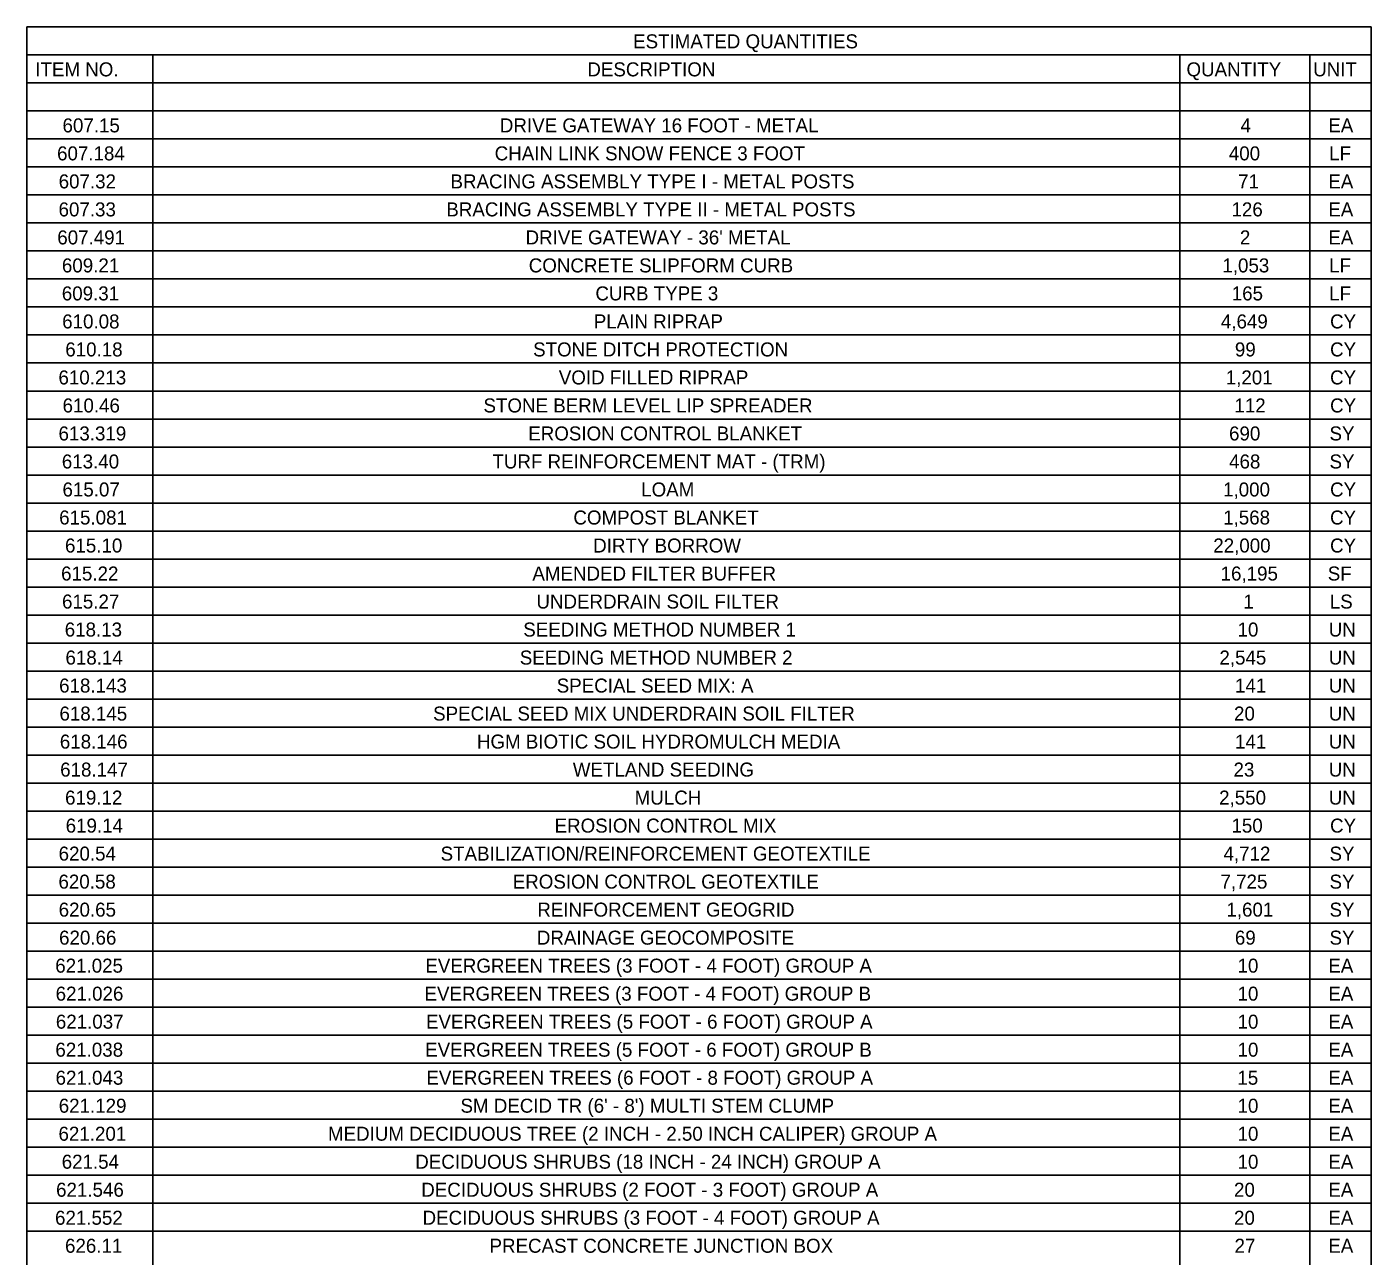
# Model space of a CAD drawing. Extents: x -18.7 to 5.6, y -2.7 to 4.
# Drawn here: x -6.23 to -5.286, y 0.046 to 0.91 of the extents above; entities that cross this region are included whole.
import ezdxf

# ---------------------------------------------------------------- set-up
doc = ezdxf.new("R2010")
doc.units = 0
doc.layers.add('ANNOTATION', color=7, linetype='Continuous')
doc.layers.add('BORDER', color=7, linetype='Continuous')

msp = doc.modelspace()

# ---------------------------------------------------------------- linework, layer by layer
at = {"layer": 'BORDER'}
for p, q in [((-6.23036, 0.89068), (-5.28608, 0.89068)), ((-6.14178, 0.89068), (-6.14178, -0.82201)), ((-5.42047, 0.89068), (-5.42047, -0.82201)), ((-5.32908, 0.89068), (-5.32908, -0.82201)), ((-6.23036, 0.87099), (-5.28608, 0.87099)), ((-6.23036, 0.8513), (-5.28608, 0.8513)), ((-6.23036, 0.83162), (-5.28608, 0.83162)), ((-6.23036, 0.81193), (-5.28608, 0.81193)), ((-6.23036, 0.79225), (-5.28608, 0.79225)), ((-6.23036, 0.77256), (-5.28608, 0.77256)), ((-6.23036, 0.75287), (-5.28608, 0.75287)), ((-6.23036, 0.73319), (-5.28608, 0.73319)), ((-6.23036, 0.7135), (-5.28608, 0.7135)), ((-6.23036, 0.69382), (-5.28608, 0.69382)), ((-6.23036, 0.67413), (-5.28608, 0.67413)), ((-6.23036, 0.65444), (-5.28608, 0.65444)), ((-6.23036, 0.63476), (-5.28608, 0.63476)), ((-6.23036, 0.61507), (-5.28608, 0.61507)), ((-6.23036, 0.59539), (-5.28608, 0.59539)), ((-6.23036, 0.5757), (-5.28608, 0.5757)), ((-6.23036, 0.55601), (-5.28608, 0.55601)), ((-6.23036, 0.53633), (-5.28608, 0.53633)), ((-6.23036, 0.51664), (-5.28608, 0.51664)), ((-6.23036, 0.49696), (-5.28608, 0.49696)), ((-6.23036, 0.47727), (-5.28608, 0.47727)), ((-6.23036, 0.45758), (-5.28608, 0.45758)), ((-6.23036, 0.4379), (-5.28608, 0.4379)), ((-6.23036, 0.41821), (-5.28608, 0.41821)), ((-6.23036, 0.39853), (-5.28608, 0.39853)), ((-6.23036, 0.37884), (-5.28608, 0.37884)), ((-6.23036, 0.35915), (-5.28608, 0.35915)), ((-6.23036, 0.33947), (-5.28608, 0.33947)), ((-6.23036, 0.31978), (-5.28608, 0.31978)), ((-6.23036, 0.3001), (-5.28608, 0.3001)), ((-6.23036, 0.28041), (-5.28608, 0.28041)), ((-6.23036, 0.26072), (-5.28608, 0.26072)), ((-6.23036, 0.24104), (-5.28608, 0.24104)), ((-6.23036, 0.22135), (-5.28608, 0.22135)), ((-6.23036, 0.20167), (-5.28608, 0.20167)), ((-6.23036, 0.18198), (-5.28608, 0.18198)), ((-6.23036, 0.16229), (-5.28608, 0.16229)), ((-6.23036, 0.14261), (-5.28608, 0.14261)), ((-6.23036, 0.12292), (-5.28608, 0.12292)), ((-6.23036, 0.10324), (-5.28608, 0.10324)), ((-6.23036, 0.08355), (-5.28608, 0.08355)), ((-6.23036, 0.06386), (-5.28608, 0.06386))]:
    msp.add_line(p, q, dxfattribs=at)
msp.add_lwpolyline([(-6.23036, 0.91036), (-5.28608, 0.91036), (-5.28608, -0.82201), (-6.23036, -0.82201)], close=True, dxfattribs=at)

# ---------------------------------------------------------------- texts
at = {"layer": 'ANNOTATION'}
for s, height, p in [('607.15', 0.009843, (-6.20532, 0.83621)), ('DRIVE GATEWAY 16 FOOT - METAL', 0.009843, (-5.8981, 0.83621)), ('4', 0.00984, (-5.37782, 0.83621)), ('EA', 0.009843, (-5.31615, 0.83621)), ('607.184', 0.009843, (-6.20916, 0.81653)), ('CHAIN LINK SNOW FENCE 3 FOOT', 0.009843, (-5.90174, 0.81653)), ('400', 0.009843, (-5.38603, 0.81653)), ('LF', 0.009843, (-5.31553, 0.81653)), ('607.32', 0.009843, (-6.20803, 0.79684)), ('BRACING ASSEMBLY TYPE I - METAL POSTS', 0.009843, (-5.9328, 0.79684)), ('71', 0.009843, (-5.37953, 0.79684)), ('EA', 0.009843, (-5.31615, 0.79684)), ('607.33', 0.009843, (-6.20811, 0.77716)), ('BRACING ASSEMBLY TYPE II - METAL POSTS', 0.009843, (-5.93572, 0.77716)), ('126', 0.009843, (-5.38417, 0.77716)), ('EA', 0.009843, (-5.31615, 0.77716)), ('607.491', 0.009843, (-6.209, 0.75747)), ("DRIVE GATEWAY - 36' METAL", 0.009843, (-5.88006, 0.75747)), ('2', 0.00984, (-5.37825, 0.75747)), ('EA', 0.009843, (-5.31615, 0.75747)), ('609.21', 0.009843, (-6.20575, 0.73778)), ('CONCRETE SLIPFORM CURB', 0.009843, (-5.87782, 0.73778)), ('1,053', 0.009843, (-5.39056, 0.73778)), ('LF', 0.009843, (-5.31553, 0.73778)), ('609.31', 0.009843, (-6.20582, 0.7181)), ('CURB TYPE 3', 0.009843, (-5.83098, 0.7181)), ('165', 0.009843, (-5.38398, 0.7181)), ('LF', 0.009843, (-5.31553, 0.7181)), ('610.08', 0.009843, (-6.20555, 0.69841)), ('PLAIN RIPRAP', 0.009843, (-5.83213, 0.69841)), ('4,649', 0.009843, (-5.39161, 0.69841)), ('CY', 0.009843, (-5.31491, 0.69841)), ('610.18', 0.009843, (-6.20338, 0.67873)), ('STONE DITCH PROTECTION', 0.009843, (-5.87476, 0.67873)), ('99', 0.009843, (-5.38177, 0.67873)), ('CY', 0.009843, (-5.31491, 0.67873)), ('610.213', 0.009843, (-6.20818, 0.65904)), ('VOID FILLED RIPRAP', 0.009843, (-5.8567, 0.65904)), ('1,201', 0.009843, (-5.3882, 0.65904)), ('CY', 0.009843, (-5.31491, 0.65904)), ('610.46', 0.009843, (-6.20528, 0.63935)), ('STONE BERM LEVEL LIP SPREADER', 0.009843, (-5.90962, 0.63935)), ('112', 0.009843, (-5.38212, 0.63935)), ('CY', 0.009843, (-5.31491, 0.63935)), ('613.319', 0.009843, (-6.20815, 0.61967)), ('EROSION CONTROL BLANKET', 0.009843, (-5.87816, 0.61967)), ('690', 0.009843, (-5.38588, 0.61967)), ('SY', 0.009843, (-5.3153, 0.61967)), ('613.40', 0.009843, (-6.20582, 0.59998)), ('TURF REINFORCEMENT MAT - (TRM)', 0.009843, (-5.90331, 0.59998)), ('468', 0.009843, (-5.38584, 0.59998)), ('SY', 0.009843, (-5.3153, 0.59998)), ('615.07', 0.009843, (-6.20536, 0.5803)), ('LOAM', 0.009843, (-5.79884, 0.5803)), ('1,000', 0.009843, (-5.39006, 0.5803)), ('CY', 0.009843, (-5.31491, 0.5803)), ('615.081', 0.009843, (-6.20768, 0.56061)), ('COMPOST BLANKET', 0.009843, (-5.84646, 0.56061)), ('1,568', 0.009843, (-5.39002, 0.56061)), ('CY', 0.009843, (-5.31491, 0.56061)), ('615.10', 0.009843, (-6.20358, 0.54092)), ('DIRTY BORROW', 0.009843, (-5.83255, 0.54092)), ('22,000', 0.009843, (-5.39696, 0.54092)), ('CY', 0.009843, (-5.31491, 0.54092)), ('615.22', 0.009843, (-6.20633, 0.52124)), ('AMENDED FILTER BUFFER ', 0.009843, (-5.87526, 0.52124)), ('16,195', 0.009843, (-5.3918, 0.52124)), ('SF', 0.009843, (-5.31654, 0.52124)), ('615.27', 0.009843, (-6.20567, 0.50155)), ('UNDERDRAIN SOIL FILTER', 0.009843, (-5.87243, 0.50155)), ('1', 0.00984, (-5.37581, 0.50155)), ('LS', 0.009843, (-5.31511, 0.50155)), ('618.13', 0.009843, (-6.20377, 0.48187)), ('SEEDING METHOD NUMBER 1', 0.009843, (-5.88167, 0.48187)), ('10', 0.009843, (-5.37991, 0.48187)), ('UN', 0.009843, (-5.31584, 0.48187)), ('618.14', 0.009843, (-6.20326, 0.46218)), ('SEEDING METHOD NUMBER 2', 0.009843, (-5.88411, 0.46218)), ('2,545', 0.009843, (-5.39265, 0.46218)), ('UN', 0.009843, (-5.31584, 0.46218)), ('618.143', 0.009843, (-6.20772, 0.44249)), ('SPECIAL SEED MIX: A', 0.009843, (-5.85818, 0.44249)), ('141', 0.009843, (-5.38169, 0.44249)), ('UN', 0.009843, (-5.31584, 0.44249)), ('618.145', 0.009843, (-6.20749, 0.42281)), ('SPECIAL SEED MIX UNDERDRAIN SOIL FILTER', 0.009843, (-5.94501, 0.42281)), ('20', 0.009843, (-5.38239, 0.42281)), ('UN', 0.009843, (-5.31584, 0.42281)), ('618.146', 0.009843, (-6.20722, 0.40312)), ('HGM BIOTIC SOIL HYDROMULCH MEDIA', 0.009843, (-5.91423, 0.40312)), ('141', 0.009843, (-5.38169, 0.40312)), ('UN', 0.009843, (-5.31584, 0.40312)), ('618.147', 0.009843, (-6.20698, 0.38344)), ('WETLAND SEEDING', 0.009843, (-5.84686, 0.38344)), ('23', 0.009843, (-5.38274, 0.38344)), ('UN', 0.009843, (-5.31584, 0.38344)), ('619.12', 0.009843, (-6.20354, 0.36375)), ('MULCH', 0.009843, (-5.80343, 0.36375)), ('2,550', 0.009843, (-5.39285, 0.36375)), ('UN', 0.009843, (-5.31584, 0.36375)), ('619.14', 0.009843, (-6.20311, 0.34406)), ('EROSION CONTROL MIX', 0.009843, (-5.85968, 0.34406)), ('150', 0.009843, (-5.38418, 0.34406)), ('CY', 0.009843, (-5.31491, 0.34406)), ('620.54', 0.009843, (-6.20807, 0.32438)), ('STABILIZATION/REINFORCEMENT GEOTEXTILE', 0.009843, (-5.93973, 0.32438)), ('4,712', 0.009843, (-5.38979, 0.32438)), ('SY', 0.009843, (-5.3153, 0.32438)), ('620.58', 0.009843, (-6.20819, 0.30469)), ('EROSION CONTROL GEOTEXTILE', 0.009843, (-5.88907, 0.30469)), ('7,725', 0.009843, (-5.39188, 0.30469)), ('SY', 0.009843, (-5.3153, 0.30469)), ('620.65', 0.009843, (-6.20803, 0.28501)), ('REINFORCEMENT GEOGRID', 0.009843, (-5.8718, 0.28501)), ('1,601', 0.009843, (-5.38773, 0.28501)), ('SY', 0.009843, (-5.3153, 0.28501)), ('620.66', 0.009843, (-6.20776, 0.26532)), ('DRAINAGE GEOCOMPOSITE', 0.009843, (-5.87212, 0.26532)), ('69', 0.009843, (-5.38177, 0.26532)), ('SY', 0.009843, (-5.3153, 0.26532)), ('621.025', 0.009843, (-6.21043, 0.24563)), ('EVERGREEN TREES (3 FOOT - 4 FOOT) GROUP A', 0.009843, (-5.95048, 0.24563)), ('10', 0.009843, (-5.37991, 0.24563)), ('EA', 0.009843, (-5.31615, 0.24563)), ('EVERGREEN TREES (3 FOOT - 4 FOOT) GROUP B', 0.009843, (-5.95106, 0.22595)), ('621.026', 0.009843, (-6.21016, 0.22595)), ('10', 0.009843, (-5.37991, 0.22595)), ('EA', 0.009843, (-5.31615, 0.22595)), ('621.037', 0.009843, (-6.21001, 0.20626)), ('EVERGREEN TREES (5 FOOT - 6 FOOT) GROUP A', 0.009843, (-5.95002, 0.20626)), ('10', 0.009843, (-5.37991, 0.20626)), ('EA', 0.009843, (-5.31615, 0.20626)), ('621.038', 0.009843, (-6.21035, 0.18658)), ('EVERGREEN TREES (5 FOOT - 6 FOOT) GROUP B', 0.009843, (-5.9506, 0.18658)), ('10', 0.009843, (-5.37991, 0.18658)), ('EA', 0.009843, (-5.31615, 0.18658)), ('621.043', 0.009843, (-6.2102, 0.16689)), ('EVERGREEN TREES (6 FOOT - 8 FOOT) GROUP A', 0.009843, (-5.94971, 0.16689)), ('15', 0.009843, (-5.38003, 0.16689)), ('EA', 0.009843, (-5.31615, 0.16689)), ('621.129', 0.009843, (-6.20799, 0.1472)), ("SM DECID TR (6' - 8') MULTI STEM CLUMP", 0.009843, (-5.92579, 0.1472)), ('10', 0.009843, (-5.37991, 0.1472)), ('EA', 0.009843, (-5.31615, 0.1472)), ('621.201', 0.009843, (-6.20815, 0.12752)), ('MEDIUM DECIDUOUS TREE (2 INCH - 2.50 INCH CALIPER) GROUP A', 0.009843, (-6.01886, 0.12752)), ('10', 0.009843, (-5.37991, 0.12752)), ('EA', 0.009843, (-5.31615, 0.12752)), ('621.54', 0.009843, (-6.2059, 0.10783)), ('DECIDUOUS SHRUBS (18 INCH - 24 INCH) GROUP A', 0.009843, (-5.95755, 0.10783)), ('10', 0.009843, (-5.37991, 0.10783)), ('EA', 0.009843, (-5.31615, 0.10783)), ('621.546', 0.009843, (-6.20985, 0.08815)), ('DECIDUOUS SHRUBS (2 FOOT - 3 FOOT) GROUP A', 0.009843, (-5.95334, 0.08815)), ('20', 0.009843, (-5.38239, 0.08815)), ('EA', 0.009843, (-5.31615, 0.08815)), ('621.552', 0.009843, (-6.21059, 0.06846)), ('DECIDUOUS SHRUBS (3 FOOT - 4 FOOT) GROUP A', 0.009843, (-5.95241, 0.06846)), ('20', 0.009843, (-5.38239, 0.06846)), ('EA', 0.009843, (-5.31615, 0.06846)), ('626.11', 0.009843, (-6.20357, 0.04877)), ('PRECAST CONCRETE JUNCTION BOX', 0.009843, (-5.90537, 0.04877)), ('27', 0.009843, (-5.38201, 0.04877)), ('EA', 0.009843, (-5.31615, 0.04877))]:
    msp.add_text(s, height=height, dxfattribs=at).set_placement(p)
at = {"layer": 'BORDER'}
for s, height, p in [('ESTIMATED QUANTITIES', 0.0098425, (-5.80451, 0.89527)), ('ITEM NO.', 0.009843, (-6.22446, 0.87558)), ('DESCRIPTION', 0.0098425, (-5.83666, 0.87558)), ('QUANTITY', 0.009843, (-5.41578, 0.87558)), ('UNIT', 0.009843, (-5.32677, 0.87558))]:
    msp.add_text(s, height=height, dxfattribs=at).set_placement(p)

doc.saveas('drawing.dxf')
